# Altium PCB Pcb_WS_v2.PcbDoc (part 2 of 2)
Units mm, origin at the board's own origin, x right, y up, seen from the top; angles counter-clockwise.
Board outline 100 x 100 mm, 2 copper layers (Top Layer, Bottom Layer); 79 components, 52 nets, 324 pads, 930 vias.
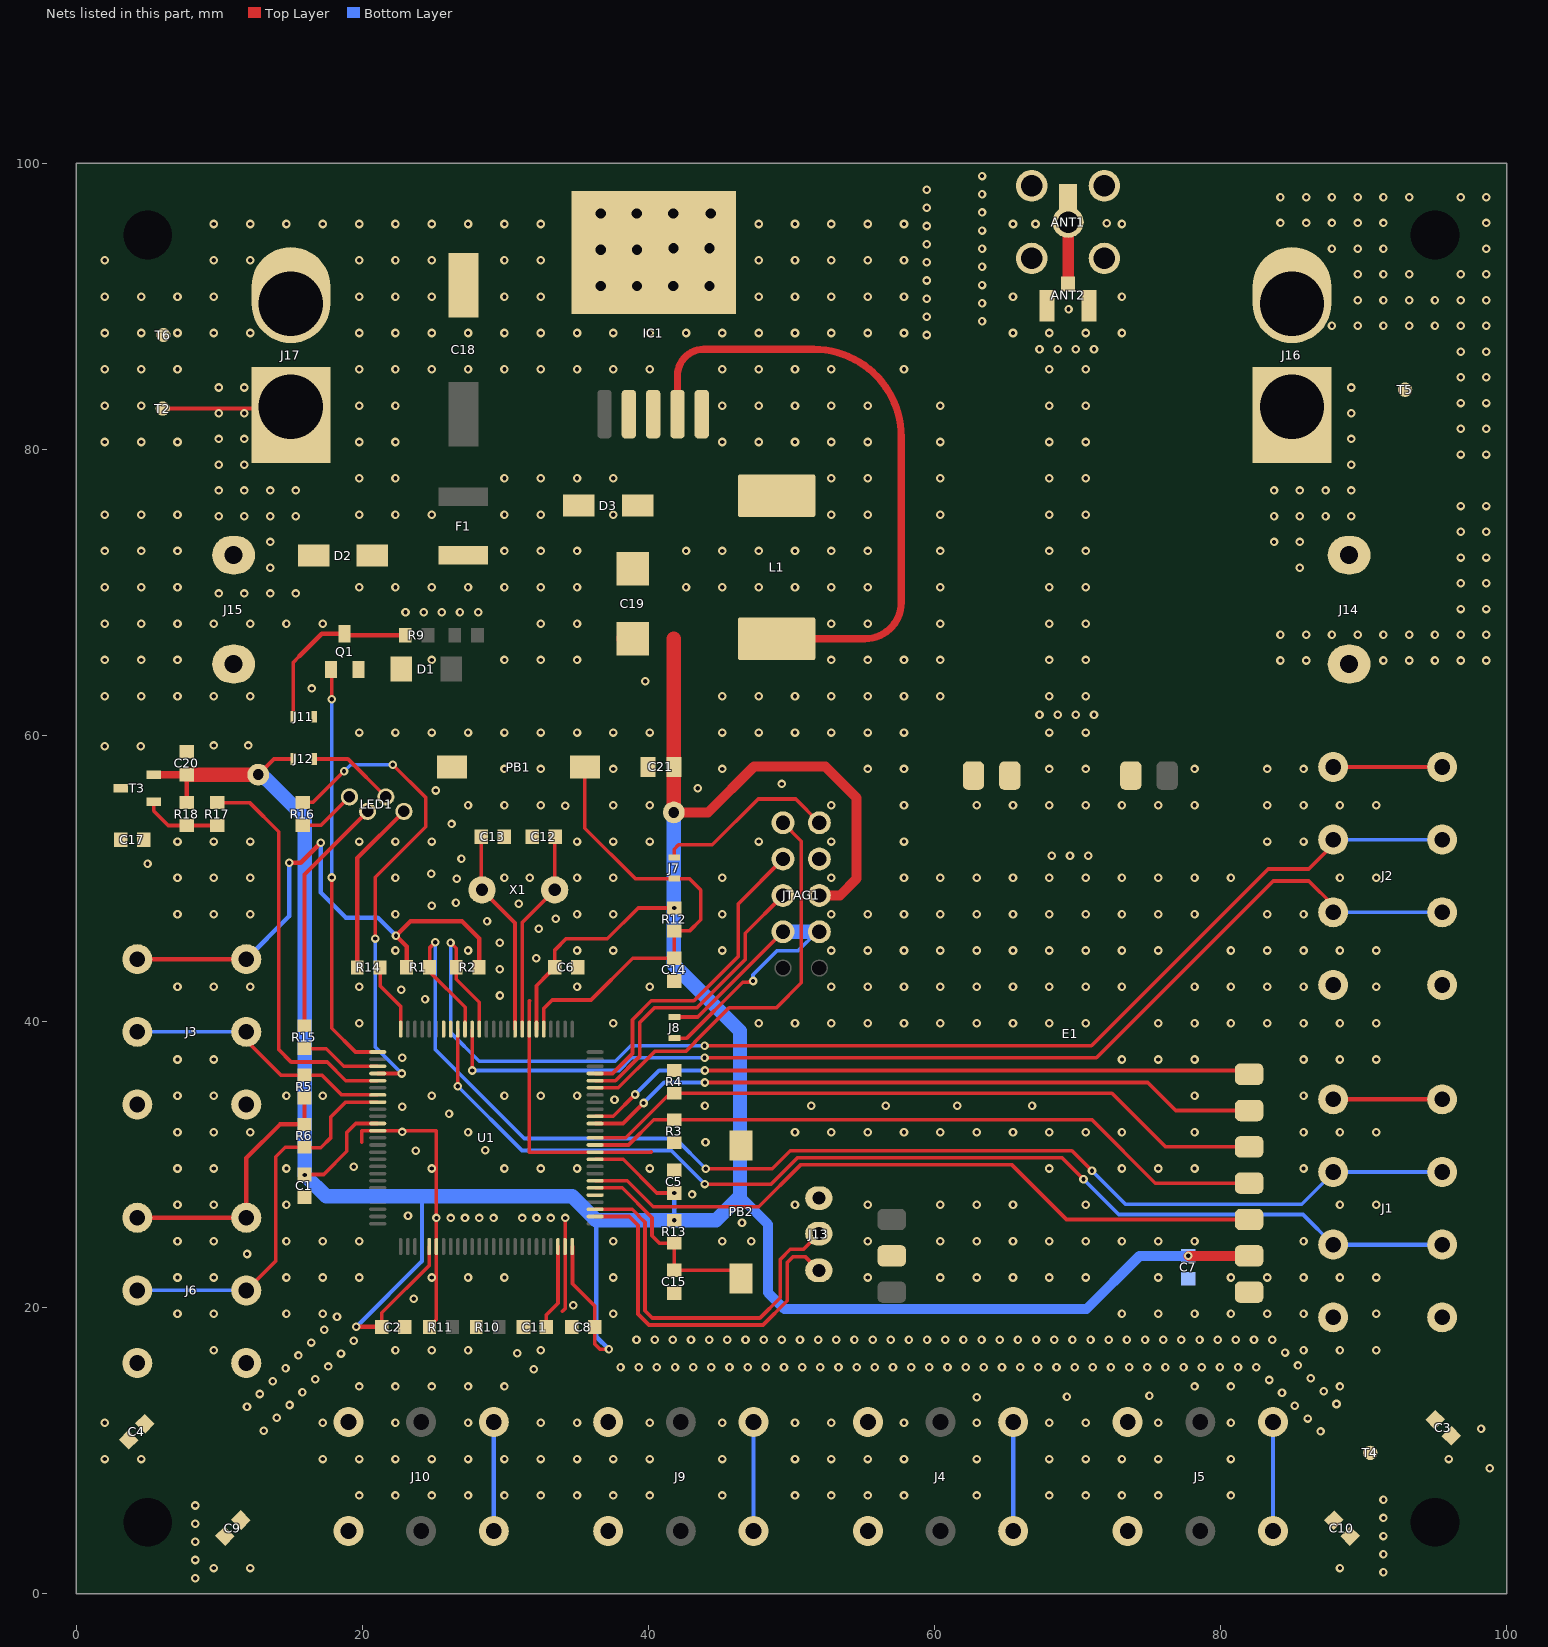
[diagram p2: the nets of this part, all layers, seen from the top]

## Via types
v1: diameter 0.6, hole 0.3, Top Layer to Bottom Layer, tented both sides, 918 vias
v2: diameter 1.27, hole 0.711, Top Layer to Bottom Layer, 12 vias

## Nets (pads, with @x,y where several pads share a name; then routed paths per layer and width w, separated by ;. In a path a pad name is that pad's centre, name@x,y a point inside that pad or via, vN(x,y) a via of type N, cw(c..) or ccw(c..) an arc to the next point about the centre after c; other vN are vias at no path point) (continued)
GND: ANT1.2 ANT2.2 C1.2 C2.2 C3.2 C4.2 C5.2 C6.2 C7.2 C8.2 C9.1 C10.1 C11.2 C12.1 C13.1 C14.1 C15.1 C17.1 C18.2 C19.2 C20.1 C21.1 D1.2 D3.2 E1.7 E1.9 E1.15 E1.16 E1.17 IC1.3 IC1.5 IC1.6 J1.4 J2.4 J3.1 J4.3 J5.3 J6.1 J9.3 J10.3 J11.2 J13.3 J15.1 J17.1 JTAG1.4 PB1.2 PB2.2 Q1.2 R3.1 R4.1 R10.2 R11.2 T6.1 U1.11 U1.32 U1.62 U1.81 U1.99 | length 45.7
  Top Layer w0.25: 19.953,31.559 19.953,32.372 U1.62@21.075,32.372 25.175,32.372 v1(25.175,26.272) U1.81@25.175,24.272 25.175,19.165 25.029,19.019 25.014,19.019 24.689,18.694 R11.2@24.689,18.644 ; 31.683,41.449 31.675,41.449 U1.32@31.675,39.472 31.675,30.872 U1.11@36.275,30.872 40.188,30.872 40.188,30.913 ; 33.988,19.75 34.175,19.938 U1.99@34.175,24.272 v1(34.175,26.272)
  other v1: 8.309,1.081 91.392,1.487 9.611,1.788 12.151,1.788 88.351,1.788 8.309,2.351 91.392,2.757 8.309,3.621 91.392,4.027 8.309,4.891 91.392,5.297 8.309,6.161 91.392,6.567 19.771,6.868 22.311,6.868 24.851,6.868 27.391,6.868 29.931,6.868 32.471,6.868 35.011,6.868 37.551,6.868 40.091,6.868 45.171,6.868 50.251,6.868 52.791,6.868 55.331,6.868 57.871,6.868 62.951,6.868 68.031,6.868 70.571,6.868 73.111,6.868 75.651,6.868 80.731,6.868 98.831,8.763 1.991,9.408 4.531,9.408 17.231,9.408 19.771,9.408 22.311,9.408 24.851,9.408 27.391,9.408 29.931,9.408 32.471,9.408 35.011,9.408 37.551,9.408 40.091,9.408 45.171,9.408 50.251,9.408 52.791,9.408 55.331,9.408 57.871,9.408 62.951,9.408 68.031,9.408 70.571,9.408 73.111,9.408 75.651,9.408 80.731,9.408 95.971,9.408 86.997,11.344 13.109,11.394 98.222,11.521 1.991,11.948 17.231,11.948 22.311,11.948 27.391,11.948 32.471,11.948 35.011,11.948 40.091,11.948 45.171,11.948 50.251,11.948 52.791,11.948 57.871,11.948 62.951,11.948 68.031,11.948 70.571,11.948 75.651,11.948 80.731,11.948 86.098,12.243 14.008,12.293 11.931,13.062 85.199,13.142 14.907,13.192 88.112,13.26 62.967,13.741 69.266,13.767 75.032,13.843 12.83,13.961 84.3,14.041 15.806,14.091 87.213,14.159 19.771,14.488 22.311,14.488 24.851,14.488 27.391,14.488 29.931,14.488 78.191,14.488 80.731,14.488 88.351,14.488 13.729,14.86 83.401,14.94 16.705,14.99 86.314,15.058 31.979,15.697 14.628,15.759 38.052,15.839 39.322,15.839 40.592,15.839 41.862,15.839 43.132,15.839 44.402,15.839 45.672,15.839 46.942,15.839 48.212,15.839 49.482,15.839 50.752,15.839 52.022,15.839 53.292,15.839 54.562,15.839 55.832,15.839 57.102,15.839 58.372,15.839 59.642,15.839 60.912,15.839 62.182,15.839 63.452,15.839 64.722,15.839 65.992,15.839 67.262,15.839 68.532,15.839 69.802,15.839 71.072,15.839 72.342,15.839 73.612,15.839 74.882,15.839 76.152,15.839 77.422,15.839 78.692,15.839 79.962,15.839 81.232,15.839 82.502,15.839 17.604,15.889 85.415,15.957 15.527,16.658 18.503,16.788 30.836,16.815 84.516,16.856 9.611,17.028 22.311,17.028 24.851,17.028 27.391,17.028 32.471,17.028 85.811,17.028 88.351,17.028 90.891,17.028 16.426,17.557 19.402,17.687 39.167,17.755 40.437,17.755 41.707,17.755 42.977,17.755 44.247,17.755 45.517,17.755 46.787,17.755 48.057,17.755 49.327,17.755 50.597,17.755 51.867,17.755 53.137,17.755 54.407,17.755 55.677,17.755 56.947,17.755 58.217,17.755 59.487,17.755 60.757,17.755 62.027,17.755 63.297,17.755 64.567,17.755 65.837,17.755 67.107,17.755 68.377,17.755 69.647,17.755 70.917,17.755 72.187,17.755 73.457,17.755 74.727,17.755 75.997,17.755 77.267,17.755 78.537,17.755 79.807,17.755 81.077,17.755 82.347,17.755 83.617,17.755 17.325,18.456 18.224,19.355 7.071,19.568 9.611,19.568 14.691,19.568 17.231,19.568 37.551,19.568 73.111,19.568 75.651,19.568 78.191,19.568 80.731,19.568 83.271,19.568 85.811,19.568 90.891,19.568 34.747,20.159 23.597,20.625 7.071,22.108 9.611,22.108 14.691,22.108 17.231,22.108 19.771,22.108 24.851,22.108 27.391,22.108 29.931,22.108 37.551,22.108 55.331,22.108 60.411,22.108 62.951,22.108 65.491,22.108 68.031,22.108 70.571,22.108 75.651,22.108 80.731,22.108 83.271,22.108 85.811,22.108 88.351,22.108 90.891,22.108 11.938,23.749 7.071,24.648 9.611,24.648 14.691,24.648 17.231,24.648 19.771,24.648 37.551,24.648 45.171,24.648 47.193,24.648 55.331,24.648 60.411,24.648 62.951,24.648 65.491,24.648 68.031,24.648 70.571,24.648 73.111,24.648 75.651,24.648 78.191,24.648 85.811,24.648 46.545,25.933 26.175,26.272 27.175,26.272 28.175,26.272 29.175,26.272 31.175,26.272 32.175,26.272 33.175,26.272 23.188,26.415 7.071,27.188 9.611,27.188 14.691,27.188 50.251,27.188 55.331,27.188 60.411,27.188 62.951,27.188 65.491,27.188 70.571,27.188 88.351,27.188 90.891,27.188 43.053,27.915 7.071,29.728 9.611,29.728 14.691,29.728 24.851,29.728 29.931,29.728 32.471,29.728 35.011,29.728 40.091,29.728 68.031,29.728 73.111,29.728 75.651,29.728 78.191,29.728 85.811,29.728 19.396,29.845 23.723,30.963 28.6,31.013 43.993,31.572 7.071,32.268 9.611,32.268 12.151,32.268 27.391,32.268 50.251,32.268 52.791,32.268 55.331,32.268 57.871,32.268 60.411,32.268 62.951,32.268 65.491,32.268 68.031,32.268 70.571,32.268 73.111,32.268 78.191,32.268 85.811,32.268 88.351,32.268 90.891,32.268 22.784,32.283 26.06,33.553 22.784,34.036 43.953,34.112 51.393,34.112 56.591,34.122 61.595,34.122 66.827,34.122 37.627,34.544 7.071,34.808 9.611,34.808 14.691,34.808 17.231,34.808 24.851,34.808 29.931,34.808 32.471,34.808 35.011,34.808 78.191,34.808 85.811,34.808 7.071,37.348 9.611,37.348 73.111,37.348 75.651,37.348 78.191,37.348 85.811,37.348 88.351,37.348 90.891,37.348 22.784,37.472 19.771,39.888 37.551,39.888 47.711,39.888 50.251,39.888 52.791,39.888 55.331,39.888 57.871,39.888 60.411,39.888 62.951,39.888 65.491,39.888 68.031,39.888 70.571,39.888 75.651,39.888 78.191,39.888 80.731,39.888 83.271,39.888 85.811,39.888 88.351,39.888 90.891,39.888 24.384,41.554 29.616,41.823 22.708,42.227 7.071,42.428 9.611,42.428 12.151,42.428 19.771,42.428 35.011,42.428 40.091,42.428 52.791,42.428 55.331,42.428 57.871,42.428 60.411,42.428 62.951,42.428 65.491,42.428 68.031,42.428 70.571,42.428 73.111,42.428 78.191,42.428 80.731,42.428 83.271,42.428 85.811,42.428 90.891,42.428 29.608,43.663 32.148,44.435 22.311,44.968 27.391,44.968 35.011,44.968 37.551,44.968 45.171,44.968 52.791,44.968 55.331,44.968 57.871,44.968 60.411,44.968 62.951,44.968 65.491,44.968 68.031,44.968 70.571,44.968 73.111,44.968 75.651,44.968 80.731,44.968 83.271,44.968 85.811,44.968 88.351,44.968 90.891,44.968 29.608,45.518 32.334,46.482 28.72,47.015 33.528,47.196 7.071,47.508 9.611,47.508 12.151,47.508 22.311,47.508 35.011,47.508 37.551,47.508 45.171,47.508 52.791,47.508 55.331,47.508 57.871,47.508 60.411,47.508 62.951,47.508 65.491,47.508 68.031,47.508 70.571,47.508 73.111,47.508 75.651,47.508 78.191,47.508 83.271,47.508 85.811,47.508 24.841,48.108 30.925,48.235 26.543,48.311 26.594,49.998 7.071,50.048 9.611,50.048 12.151,50.048 22.311,50.048 29.931,50.048 35.011,50.048 37.551,50.048 45.171,50.048 52.791,50.048 57.871,50.048 60.411,50.048 62.951,50.048 65.491,50.048 68.031,50.048 70.571,50.048 73.111,50.048 75.651,50.048 78.191,50.048 80.731,50.048 88.351,50.048 90.891,50.048 31.699,50.063 24.816,50.343 4.978,51.036 26.924,51.384 68.209,51.597 69.479,51.597 70.749,51.597 7.071,52.588 9.611,52.588 12.151,52.588 19.771,52.588 22.311,52.588 24.851,52.588 35.011,52.588 37.551,52.588 40.091,52.588 47.711,52.588 52.791,52.588 57.871,52.588 83.271,52.588 85.811,52.588 26.238,53.822 34.188,55.093 27.391,55.128 29.931,55.128 32.471,55.128 37.551,55.128 40.091,55.128 52.791,55.128 57.871,55.128 62.951,55.128 65.491,55.128 68.031,55.128 70.571,55.128 73.111,55.128 75.651,55.128 78.191,55.128 83.271,55.128 85.811,55.128 88.351,55.128 90.891,55.128 25.121,56.159 43.444,56.312 49.327,56.617 29.931,57.668 32.471,57.668 37.551,57.668 45.171,57.668 55.331,57.668 57.871,57.668 68.031,57.668 70.571,57.668 78.191,57.668 83.271,57.668 85.811,57.668 1.991,59.258 4.496,59.258 9.601,59.309 12.014,59.309 19.771,60.208 22.311,60.208 24.851,60.208 27.391,60.208 29.931,60.208 32.471,60.208 35.011,60.208 37.551,60.208 40.091,60.208 45.171,60.208 47.711,60.208 50.251,60.208 52.791,60.208 55.331,60.208 57.871,60.208 68.031,60.208 70.571,60.208 67.344,61.457 68.614,61.457 69.884,61.457 71.154,61.457 1.991,62.748 4.531,62.748 7.071,62.748 9.611,62.748 12.151,62.748 45.171,62.748 47.711,62.748 50.251,62.748 52.791,62.748 55.331,62.748 57.871,62.748 60.411,62.748 68.031,62.748 70.571,62.748 16.459,63.297 39.776,63.805 1.991,65.288 4.531,65.288 7.071,65.288 24.851,65.288 29.931,65.288 32.471,65.288 35.011,65.288 52.791,65.288 55.331,65.288 57.871,65.288 60.411,65.288 68.031,65.288 70.571,65.288 1.991,67.828 4.531,67.828 7.071,67.828 9.611,67.828 12.151,67.828 14.691,67.828 17.231,67.828 32.471,67.828 35.011,67.828 52.791,67.828 55.331,67.828 60.411,67.828 68.031,67.828 70.571,67.828 23.012,68.631 24.282,68.631 25.552,68.631 26.822,68.631 28.092,68.631 1.991,70.368 4.531,70.368 7.071,70.368 19.771,70.368 22.311,70.368 24.851,70.368 27.391,70.368 29.931,70.368 32.471,70.368 35.011,70.368 42.631,70.368 45.171,70.368 47.711,70.368 50.251,70.368 52.791,70.368 55.331,70.368 60.411,70.368 68.031,70.368 70.571,70.368 1.991,72.908 4.531,72.908 7.071,72.908 29.931,72.908 32.471,72.908 35.011,72.908 42.631,72.908 45.171,72.908 47.711,72.908 50.251,72.908 52.791,72.908 55.331,72.908 60.411,72.908 68.031,72.908 70.571,72.908 1.991,75.448 4.531,75.448 7.071,75.448 19.771,75.448 22.311,75.448 24.851,75.448 29.931,75.448 32.471,75.448 37.551,75.448 52.791,75.448 55.331,75.448 60.411,75.448 68.031,75.448 70.571,75.448 19.771,77.988 22.311,77.988 29.931,77.988 32.471,77.988 35.011,77.988 37.551,77.988 52.791,77.988 55.331,77.988 60.411,77.988 68.031,77.988 70.571,77.988 1.991,80.528 4.531,80.528 7.071,80.528 19.771,80.528 22.311,80.528 45.171,80.528 47.711,80.528 50.251,80.528 52.791,80.528 55.331,80.528 60.411,80.528 68.031,80.528 70.571,80.528 1.991,83.068 4.531,83.068 19.771,83.068 22.311,83.068 45.171,83.068 47.711,83.068 50.251,83.068 52.791,83.068 55.331,83.068 60.411,83.068 68.031,83.068 70.571,83.068 1.991,85.608 4.531,85.608 7.071,85.608 19.771,85.608 22.311,85.608 24.851,85.608 27.391,85.608 29.931,85.608 32.471,85.608 35.011,85.608 37.551,85.608 40.091,85.608 45.171,85.608 47.711,85.608 50.251,85.608 52.791,85.608 57.871,85.608 68.031,85.608 70.571,85.608 67.344,87.01 68.614,87.01 69.884,87.01 71.154,87.01 59.471,88.007 1.991,88.148 4.531,88.148 7.071,88.148 9.611,88.148 12.151,88.148 19.771,88.148 22.311,88.148 24.851,88.148 27.391,88.148 29.931,88.148 32.471,88.148 35.011,88.148 37.551,88.148 40.091,88.148 42.631,88.148 45.171,88.148 47.711,88.148 50.251,88.148 52.791,88.148 55.331,88.148 57.871,88.148 65.491,88.148 68.031,88.148 70.571,88.148 73.111,88.148 63.332,88.961 59.471,89.277 69.377,89.799 63.332,90.231 59.471,90.547 1.991,90.688 4.531,90.688 7.071,90.688 9.611,90.688 19.771,90.688 22.311,90.688 24.851,90.688 29.931,90.688 32.471,90.688 47.711,90.688 50.251,90.688 52.791,90.688 55.331,90.688 57.871,90.688 65.491,90.688 73.111,90.688 63.332,91.501 59.471,91.817 63.332,92.771 59.471,93.087 1.991,93.228 9.611,93.228 12.151,93.228 19.771,93.228 22.311,93.228 24.851,93.228 29.931,93.228 32.471,93.228 47.711,93.228 50.251,93.228 52.791,93.228 55.331,93.228 57.871,93.228 63.332,94.041 59.471,94.357 63.332,95.311 59.471,95.627 9.611,95.768 12.151,95.768 14.691,95.768 17.231,95.768 19.771,95.768 22.311,95.768 24.851,95.768 27.391,95.768 29.931,95.768 32.471,95.768 47.711,95.768 50.251,95.768 52.791,95.768 55.331,95.768 57.871,95.768 65.491,95.768 67.066,95.768 73.111,95.768 72.044,95.819 63.332,96.581 59.471,96.897 63.332,97.851 59.471,98.167 63.332,99.121
  other v2: 36.662,91.424 39.202,91.424 41.742,91.424 44.282,91.424 36.662,93.964 39.202,93.964 41.752,94.069 44.282,94.069 36.662,96.504 39.18,96.504 41.742,96.504 44.355,96.504
GND-SOLAR: J14.2 J16.1
  other v1: 84.193,65.246 85.993,65.246 91.393,65.246 93.193,65.246 94.993,65.246 96.793,65.246 98.593,65.246 84.193,67.046 85.993,67.046 87.793,67.046 89.593,67.046 91.393,67.046 93.193,67.046 94.993,67.046 96.793,67.046 98.593,67.046 96.793,68.846 98.593,68.846 96.793,70.646 98.593,70.646 96.793,72.446 98.593,72.446 96.793,74.246 98.593,74.246 96.793,76.046 98.593,76.046 96.793,79.646 98.593,79.646 96.793,81.446 98.593,81.446 96.793,83.246 98.593,83.246 96.793,85.046 98.593,85.046 96.793,86.846 98.593,86.846 87.793,88.646 89.593,88.646 91.393,88.646 93.193,88.646 94.993,88.646 96.793,88.646 98.593,88.646 89.593,90.446 91.393,90.446 93.193,90.446 94.993,90.446 96.793,90.446 98.593,90.446 89.593,92.246 91.393,92.246 93.193,92.246 96.793,92.246 98.593,92.246 87.793,94.046 89.593,94.046 91.393,94.046 98.593,94.046 84.193,95.846 85.993,95.846 87.793,95.846 89.593,95.846 91.393,95.846 98.593,95.846 84.193,97.646 85.993,97.646 87.793,97.646 89.593,97.646 91.393,97.646 93.193,97.646 96.793,97.646 98.593,97.646
MISO: JTAG1.3 U1.22 | length 22.9
  Top Layer w0.254: U1.22@36.275,36.372 37.495,36.372 38.888,37.764 38.888,40.132 40.205,41.449 43.181,41.449 46.277,44.544 46.277,48.227 JTAG1.3@49.412,51.363
MOSI: JTAG1.5 U1.21 | length 21
  Top Layer w0.254: U1.21@36.275,35.872 37.694,35.872 39.382,37.559 39.382,39.928 40.409,40.955 43.386,40.955 46.771,44.34 46.771,46.181 JTAG1.5@49.412,48.823
NetANT1_1: ANT1.1 ANT2.1 pad.4 | length 4.3
  Top Layer w0.8: ANT2.1@69.341,91.562 ANT1.1@69.341,95.902
NetC11_1: C11.1 U1.98 | length 6
  Top Layer w0.254: C11.1@32.867,18.644 32.867,19.507 33.675,20.315 U1.98@33.675,24.272
NetC12_2: C12.2 U1.33 X1.1 | length 14.4
  Top Layer w0.254: U1.33@31.175,39.472 31.175,46.934 X1.1@33.448,49.207 33.448,52.919 C12.2@33.475,52.919
NetC13_2: C13.2 U1.34 X1.2 | length 14.5
  Top Layer w0.254: C13.2@28.273,52.919 C13.2@28.319,52.919 28.319,49.207 X1.2@28.368,49.207 30.675,46.9 U1.34@30.675,39.472
NetD2_1: D2.1 F1.1
NetD3_1: D3.1 IC1.2 L1.1
NetJ7_1: J7.1 JTAG1.2 | length 12.9
  Top Layer w0.254: J7.1@41.806,51.471 41.806,52.055 42.111,52.36 44.473,52.36 47.674,55.56 50.295,55.56 JTAG1.2@51.952,53.903
NetJ11_1: J11.1 Q1.3 R9.2 | length 12.5
  Top Layer w0.25: J11.1@15.159,61.308 15.159,65.112 15.591,65.544
  Top Layer w0.3: 15.591,65.544 17.161,67.114 Q1.3@18.755,67.114 18.862,67.007 R9.2@22.994,67.007
NetJ12_2: J12.2 LED1.A | length 6.1
  Top Layer w0.25: J12.2@16.633,58.362 18.989,58.362 LED1.A@21.636,55.714
NetLED1_B: LED1.B R15.2 | length 16.8
  Top Layer w0.3: R15.2@15.951,39.709 15.951,50.283 LED1.B@20.366,54.698
NetLED1_G: LED1.G R14.2 | length 12.3
  Top Layer w0.3: R14.2@19.643,43.786 19.643,51.435 LED1.G@22.906,54.698
NetLED1_R: LED1.R R16.2 | length 4.1
  Top Layer w0.25: R16.2@15.82,53.714 17.096,53.714 LED1.R@19.096,55.714
NetR17_2: R17.2 R18.2 T3.1 | length 5.5
  Top Layer w0.254: T3.1@5.41,55.364 5.41,54.732 6.428,53.714 R18.2@7.717,53.714
  Top Layer w0.3: R18.2@7.717,53.714 R17.2@9.844,53.714
ON5V: J8.1 J8.2 JTAG1.7 JTAG1.8 | length 25.9
  Top Layer w0.254: J8.2@41.825,38.847 42.691,38.847 46.605,42.76 46.995,42.76 47.005,42.77 47.25,42.77 v1(47.316,42.837) ; J8.1@41.825,40.32 43.45,40.32 JTAG1.7@49.412,46.283
  Bottom Layer w0.254: v1(47.316,42.837) 47.316,43.268 48.992,44.945 50.465,44.945 51.803,46.283 JTAG1.8@51.952,46.283
  Bottom Layer w1: JTAG1.7@49.412,46.283 JTAG1.8@51.803,46.283
Pin2Button: C15.2 PB2.1 R13.1 U1.6 | length 14.7
  Top Layer w0.254: U1.6@36.275,28.372 38.173,28.372 40.255,26.29 40.255,25.031 40.777,24.509 R13.1@41.8,24.509 C15.2@41.8,22.604 45.917,22.604 PB2.1@46.482,22.039
Pin3AUX: E1.5 U1.7 | length 49.3
  Top Layer w0.254: U1.7@36.275,28.872 38.521,28.872 40.339,27.053 47.705,27.053 50.63,29.978 65.419,29.978 69.237,26.16 E1.5@82,26.16
Pin5: U1.5
Pin6M1: E1.2 U1.15 | length 47.7
  Top Layer w0.254: U1.15@36.275,32.872 38.227,32.872 v1(39.663,34.308) ; v1(43.953,35.74) 74.907,35.74 76.867,33.78 E1.2@82,33.78
  Bottom Layer w0.254: v1(39.663,34.308) 41.096,35.74 v1(43.953,35.74)
Pin7M0: E1.1 U1.16 | length 47.2
  Top Layer w0.254: U1.16@36.275,33.372 37.539,33.372 v1(39.069,34.902) ; v1(43.953,36.58) 81.74,36.58 E1.1@82,36.32
  Bottom Layer w0.254: v1(39.069,34.902) 40.748,36.58 v1(43.953,36.58)
Pin32DS1: J6.2 R6.2 U1.58 | length 27.4
  Top Layer w0.254: J6.2@11.88,21.203 13.937,23.261 13.937,30.543 14.607,31.213 R6.2@15.947,31.213 15.982,31.178 17.087,31.178 17.798,31.889 17.798,33.337 18.833,34.372 U1.58@21.075,34.372
  Bottom Layer w0.254: J6.2@4.26,21.203 J6.2@11.88,21.203
Pin33DS2: J3.2 R5.2 U1.57 | length 19
  Top Layer w0.254: J3.2@11.88,39.283 11.88,38.671 14.293,36.258 R5.2@15.951,36.258 17.166,36.258 18.552,34.872 U1.57@21.075,34.872
  Bottom Layer w0.254: J3.2@4.26,39.283 J3.2@11.88,39.283
Pin35FET: R17.1 U1.55 | length 28.2
  Top Layer w0.25: R17.1@9.844,55.314 12.106,55.314 14.143,53.276 14.143,38.043 15.014,37.172 17.534,37.172 18.834,35.872 U1.55@21.075,35.872
Pin36Data: R16.1 U1.54 | length 33.9
  Top Layer w0.25: R16.1@15.82,55.314 15.837,55.331 16.548,55.331 v1(18.718,57.5) ; v1(20.903,45.806) 20.903,50.096 24.433,53.626 24.433,55.667 v1(22.133,57.967) ; U1.54@21.075,36.372 v1(22.75,36.372)
  Bottom Layer w0.25: v1(18.718,57.5) 19.184,57.967 v1(22.133,57.967) ; v1(20.903,45.806) 20.903,38.219 v1(22.75,36.372)
Pin37Net: R15.1 U1.53 | length 5.6
  Top Layer w0.254: R15.1@15.951,38.109 17.466,38.109 18.704,36.872 U1.53@21.075,36.872
Pin38Bug: R14.1 U1.50 | length 4.9
  Top Layer w0.254: R14.1@21.243,43.786 21.243,42.492 22.675,41.06 U1.50@22.675,39.472
Pin41EnLevelPin: Q1.1 U1.51 | length 29
  Top Layer w0.25: Q1.1@17.81,64.62 17.852,64.577 v1(17.852,62.547) ; v1(17.852,50.076) 17.852,39.535 19.515,37.872 U1.51@21.075,37.872
  Bottom Layer w0.25: v1(17.852,50.076) v1(17.852,62.547)
Pin42CLSHT1: J1.3 U1.42 | length 78.9
  Top Layer w0.254: v1(26.675,35.472) U1.42@26.675,39.472 ; v1(43.938,28.638) 48.592,28.638 50.425,30.472 68.925,30.472 v1(70.425,28.972)
  Bottom Layer w0.254: v1(26.675,35.472) 31.159,30.988 41.588,30.988 v1(43.938,28.638) ; v1(70.425,28.972) 72.882,26.514 85.769,26.514 J1.3@87.88,24.404
  Bottom Layer w0.3: J1.3@87.88,24.404 J1.3@95.5,24.404
Pin43DTSHT1: J1.2 R1.1 U1.41 | length 91.7
  Top Layer w0.254: v1(25.099,45.544) 24.698,45.142 R1.1@24.698,43.8 24.698,43.484 27.183,40.999 27.183,39.951 27.175,39.943 U1.41@27.175,39.472 ; v1(44.014,29.705) 48.658,29.705 49.925,30.972 69.613,30.972 v1(71.019,29.566)
  Bottom Layer w0.254: v1(25.099,45.544) 25.099,38.047 31.321,31.826 41.892,31.826 v1(44.014,29.705) ; v1(71.019,29.566) 73.363,27.222 85.675,27.222 87.88,29.426 J1.2@87.88,29.484 J1.2@95.5,29.484
Pin44CLSHT2: J2.3 U1.40 | length 77.4
  Top Layer w0.254: v1(27.675,36.58) U1.40@27.675,39.472 ; v1(43.925,37.472) 71.324,37.472 83.683,49.831 86.175,49.831 87.88,48.126 J2.3@87.88,47.644
  Bottom Layer w0.254: v1(27.675,36.58) 37.941,36.58 38.833,37.472 v1(43.925,37.472) ; J2.3@87.88,47.644 J2.3@95.5,47.644
Pin45DTSHT2: J2.2 R2.1 U1.39 | length 90
  Top Layer w0.254: v1(26.166,45.519) 26.566,45.119 R2.1@26.566,43.8 26.566,42.962 28.175,41.353 U1.39@28.175,39.472 ; v1(43.925,38.312) 70.976,38.312 83.335,50.671 86.175,50.671 87.88,52.376 J2.2@87.88,52.724
  Bottom Layer w0.254: v1(26.166,45.519) 26.166,39.231 28.175,37.222 37.675,37.222 38.765,38.312 v1(43.925,38.312) ; J2.2@87.88,52.724 J2.2@95.5,52.724
RESET: C14.2 J7.2 PB1.1 R12.1 U1.30 | length 32.3
  Top Layer w0.254: U1.30@32.675,39.472 32.675,40.917 33.272,41.514 35.99,41.514 38.911,44.435 C14.2@41.8,44.435 R12.1@41.8,46.34 42.873,46.34 43.66,47.127 43.66,49.196 42.859,49.998 J7.2@41.806,49.998 39.088,49.998 35.558,53.528 PB1.1@35.558,57.789
RX_2560: J13.1 U1.2 | length 26.4
  Top Layer w0.25: U1.2@36.275,26.372 38.669,26.372 39.273,25.768 39.273,19.552 40.041,18.784 48.015,18.784 49.717,20.486 49.717,23.156 50.132,23.57 50.953,23.57 J13.1@51.918,22.606
RX_Lora: E1.3 R4.2 U1.13 | length 48.6
  Top Layer w0.254: U1.13@36.275,31.872 38.412,31.872 41.527,34.986 R4.2@41.8,34.986 72.41,34.986 76.157,31.24 E1.3@82,31.24
SCK: JTAG1.1 U1.20 | length 29.2
  Top Layer w0.254: U1.20@36.275,35.372 37.893,35.372 40.454,37.933 42.63,37.933 43.258,38.56 43.258,38.588 45.642,40.972 48.956,40.972 50.696,42.712 50.696,52.619 JTAG1.1@49.412,53.903
SCL: U1.43
SDA: U1.44
TX_2560: J13.2 U1.3 | length 26.5
  Top Layer w0.25: U1.3@36.275,26.872 38.876,26.872 39.335,26.413 39.335,26.399 39.763,25.971 39.763,19.77 40.259,19.274 47.798,19.274 49.217,20.693 49.217,23.363 49.924,24.07 50.848,24.07 51.918,25.14 J13.2@51.918,25.171
TX_Lora: E1.4 R3.2 U1.12 | length 48.3
  Top Layer w0.254: U1.12@36.275,31.372 38.611,31.372 40.371,33.132 R3.2@41.8,33.132 71.015,33.132 75.447,28.7 E1.4@82,28.7
VBAT: D2.2 J15.2 J17.2 T2.1 | length 9
  Top Layer w0.254: T2.1@6.043,82.865 14.865,82.865 ccw(c14.865,83) J17.2@15,83
  other v1: 9.948,69.939 11.748,69.939 13.548,69.939 15.348,69.939 13.548,71.739 13.548,73.539 9.948,75.339 11.748,75.339 13.548,75.339 15.348,75.339 9.948,77.139 11.748,77.139 13.548,77.139 15.348,77.139 9.948,78.939 11.748,78.939 9.948,80.739 11.748,80.739 9.948,82.539 11.748,82.539 9.948,84.339 11.748,84.339
VCC: C1.1 C2.1 C5.1 C6.1 C7.1 C8.1 C19.1 C20.2 C21.2 E1.6 IC1.4 J12.1 JTAG1.6 L1.2 pad.TP-VCC R12.2 R13.2 R18.1 T3.2 U1.10 U1.31 U1.61 U1.80 U1.100 | length 295.8
  Top Layer w0.25: U1.100@34.69,24.272 34.69,21.664 36.242,20.113 C8.1@36.242,18.644 36.242,17.454 36.612,17.083 v1(37.239,17.083)
  Top Layer w0.254: C1.1@15.951,29.308 17.294,29.308 18.916,30.93 18.916,32.245 19.543,32.872 U1.61@21.075,32.872 ; C2.1@21.362,18.644 21.362,19.634 24.675,22.948 U1.80@24.675,24.272 ; U1.31@32.175,39.472 32.175,42.513 33.089,43.427 33.114,43.427 33.462,43.775 C6.1@33.462,43.8 33.462,45.011 34.235,45.783 37.13,45.783 39.288,47.94 v1(41.8,47.94) ; U1.10@36.275,30.372 38.233,30.372 40.59,28.014 v1(41.8,28.014)
  Top Layer w0.3: R18.1@7.717,55.314 C20.2@7.717,57.264 ; pad.TP-VCC@12.717,57.264 13.815,58.362 J12.1@15.159,58.362 ; v1(19.579,18.656) 21.349,18.656 C2.1@21.362,18.644
  Top Layer w0.5: T3.2@5.41,57.264 C20.2@7.717,57.264 ; IC1.4@42.031,82.475 42.031,85.167 cw(c43.872,85.167) 43.872,87.007 51.563,87.007 cw(c51.563,80.891) 57.679,80.891 57.679,69.309 cw(c55.139,69.309) 55.139,66.769 L1.2@48.969,66.769
  Top Layer w0.7: pad.TP-VCC@41.775,54.628 44.17,54.628 47.367,57.825 52.376,57.825 54.562,55.639 54.562,49.998 53.387,48.823 JTAG1.6@51.952,48.823 ; v1(77.75,23.62) E1.6@82,23.62
  Top Layer w1: C20.2@7.717,57.264 pad.TP-VCC@12.717,57.264 ; pad.TP-VCC@41.775,54.628 C21.2@41.775,57.804 41.775,66.769
  Top Layer w2.25: C19.1@38.911,66.769 C19.1@38.911,66.775
  Bottom Layer w0.3: v1(19.579,18.656) 24.175,23.252 24.175,27.78 ; 36.355,26.104 36.355,17.968 v1(37.239,17.083) ; v1(41.8,26.109) v1(41.8,28.014)
  Bottom Layer w0.7: 46.404,27.78 48.357,25.827 48.357,21.043 49.5,19.9 70.633,19.9 74.353,23.62 v1(77.75,23.62)
  Bottom Layer w1: pad.TP-VCC@12.717,57.264 12.859,57.264 13.121,57.002 13.245,57.002 15.974,54.272 v1(15.974,29.279) 17.473,27.78 24.175,27.78 34.678,27.78 36.355,26.104 44.727,26.104 46.404,27.78 46.404,39.337 41.775,43.966 pad.TP-VCC@41.775,54.628
VCC_Sensor: C3.1 C4.1 C9.2 C10.2 C17.2 J1.1 J2.1 J3.3 J4.1 J5.1 J6.3 J9.1 J10.1 R1.2 R2.2 R5.1 R6.1 T3.3 T4.1 | length 104
  Top Layer w0.3: J6.3@4.26,26.283 J6.3@11.88,26.283 11.88,30.455 14.238,32.813 R6.1@15.947,32.813 15.947,34.655 R5.1@15.951,34.658 ; J3.3@4.26,44.363 J3.3@11.88,44.363 ; v1(14.876,51.104) 15.689,51.104 v1(17.086,52.501) ; R1.2@23.098,43.8 23.098,45.245 v1(22.344,45.999) 23.36,47.015 26.967,47.015 28.166,45.815 R2.2@28.166,43.8 ; J1.1@87.88,34.564 J1.1@95.5,34.564 ; J2.1@87.88,57.804 J2.1@95.5,57.804
  Bottom Layer w0.3: J3.3@11.88,44.363 14.876,47.36 v1(14.876,51.104) ; v1(17.086,52.501) 17.086,49.021 18.839,47.269 21.074,47.269 v1(22.344,45.999) ; J10.1@29.188,4.38 J10.1@29.188,12 ; J9.1@47.348,4.38 J9.1@47.348,12 ; J4.1@65.508,4.38 J4.1@65.508,12 ; J5.1@83.668,4.38 J5.1@83.668,12
VSOLAR: J14.1 J16.2 T5.1
  other v1: 85.548,71.739 83.748,73.539 85.548,73.539 83.748,75.339 85.548,75.339 87.348,75.339 89.148,75.339 83.748,77.139 85.548,77.139 87.348,77.139 89.148,77.139 89.148,78.939 89.148,80.739 89.148,82.539 89.148,84.339
pads on no net: E1.8 E1.10 E1.11 E1.12 E1.13 E1.14 E1.18 HOLE1.1 HOLE2.1 HOLE3.1 HOLE4.1 JTAG1.9 JTAG1.10 U1.1 U1.4 U1.8 U1.9 U1.14 U1.17 U1.18 U1.19 U1.23 U1.24 U1.25 U1.26 U1.27 U1.28 U1.29 U1.35 U1.36 U1.37 U1.38 U1.45 U1.46 U1.47 U1.48 U1.49 U1.52 U1.56 U1.59 U1.60 U1.63 U1.64 U1.65 U1.66 U1.67 U1.68 U1.69 U1.70 U1.71 U1.72 U1.73 U1.74 U1.75 U1.76 U1.77 U1.78 U1.79 U1.82 U1.83 U1.84 U1.85 U1.86 U1.87 U1.88 U1.89 U1.90 U1.92 U1.93

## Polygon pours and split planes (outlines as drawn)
GND on Top Layer "AutoNaming" (solid, remove dead copper, pour order 58): 0,100 0,7.86 7.504,7.86 19.279,19.634 20.296,19.634 23.675,23.014 23.675,24.272 34.675,24.272 34.675,21.679 36.242,20.113 36.242,17.454 36.612,17.083 83.397,17.083 92.62,7.86 100,7.86 100,59.74 80.51,59.74 80.51,52.069 58.372,52.069 58.372,62.28 61.493,62.28 61.493,85.14 60.19,85.14 60.19,100
GND on Top Layer "AutoNaming" (solid, remove dead copper, pour order 40): 7.699,0 7.699,6.776 19.579,18.656 21.349,18.656 21.349,19.622 24.675,22.948 24.675,24.272 34.675,24.272 34.675,21.679 36.242,20.113 36.242,17.454 36.612,17.083 37.349,16.347 82.985,16.347 92.052,7.279 92.052,0
GND on Top Layer "AutoNaming" (solid, remove dead copper, pour order 48): 60.147,59.792 60.147,54.75 78.649,54.75 78.649,59.792 71.839,59.792 71.839,87.732 75.387,87.732 75.387,100.052 62.687,100.052 62.687,87.732 66.759,87.732 66.759,59.792
CheckLevel on Top Layer "Top Layer-NetC17_1 2" (solid, pour order 10): 25.22,84.821 28.903,84.821 28.903,75.931 25.22,75.931
GND on Top Layer "AutoNaming" (solid, pour order 60): 68.532,51.153 70.425,51.153 70.425,56.502 68.532,56.502
VCC_Sensor on Top Layer "AutoNaming" (solid, remove dead copper, pour order 20): 1,49.669 1,15.01 14.76,1.25 84.779,1.25 98.5,14.971 98.5,59.778 93.671,59.778 93.671,16.741 83.038,6.108 17.318,6.108 6.066,17.36 6.066,49.669
CheckLevel on Top Layer "Top Layer-NetC17_1" (solid, pour order 18): 28.903,79.741 cw(c29.944,79.741) 29.944,80.782 30.071,80.782 30.071,84.821 25.22,84.821 25.22,79.741
NetD3_1 on Top Layer "Top Layer-NetD3_1" (solid, pour order 16): 38.123,75.194 51.738,75.194 51.738,78.369 41.755,78.369 cw(c41.755,80.986) 39.139,80.986 39.139,83.932 ccw(c38.885,83.932) 38.885,84.186 38.377,84.186 ccw(c38.377,83.932) 38.123,83.932
CheckLevel on Top Layer "Top Layer-NetC17_1 1" (solid, pour order 12): 25.22,84.821 36.752,84.821 cw(c36.752,84.135) 37.437,84.135 37.437,81.011 cw(c37.209,81.011) 37.209,80.782 25.22,80.782
NetD2_1 on Top Layer "Top Layer-NetD2_1" (solid, pour order 8): 19.581,71.308 29.081,71.308 29.081,73.874 19.581,73.874
VBAT on Top Layer "Top Layer-VBAT" (solid, pour order 4): 17.727,71.765 cw(c15.187,71.765) 15.187,69.225 11.047,69.225 cw(c11.047,71.765) 8.507,71.765 8.507,83.145 cw(c11.047,83.145) 11.047,85.685 17.727,85.685
GND-SOLAR on Top Layer "Top Layer-GND-SOLAR" (solid, pour order 0): 82.243,90.587 82.243,96.859 cw(c84.658,96.859) 84.658,99.274 99.337,99.274 99.337,64.958 cw(c96.797,64.958) 96.797,62.418 85.367,62.418 cw(c85.367,65.542) 82.243,65.542 cw(c85.075,65.542) 85.075,68.374 93.025,68.374 ccw(c93.025,71.435) 96.086,71.435 96.086,84.211 ccw(c92.86,84.211) 92.86,87.437 84.961,87.437
no net on Top Layer "AutoNaming" (solid, pour order 26): 0,0
no net on Top Layer "AutoNaming" (solid, pour order 22): 0,0
no net on Top Layer "Top Layer-No Net" (solid, pour order 14): 38.174,83.221
GND on Bottom Layer "AutoNaming" (solid, remove dead copper, pour order 54): 0,100 0,7.899 7.578,7.899 24.175,24.495 24.175,27.78 34.678,27.78 36.355,26.104 36.355,18.854 38.143,17.066 83.414,17.066 92.581,7.899 100,7.899 100,59.74 80.51,59.74 80.51,52.12 58.372,52.12 58.372,62.28 61.493,62.28 61.493,85.14 60.19,85.14 60.19,100
GND on Bottom Layer "AutoNaming" (solid, remove dead copper, pour order 36): 7.696,0 7.696,6.773 24.175,23.252 24.175,27.78 34.678,27.78 36.355,26.104 36.355,17.968 37.976,16.347 82.993,16.347 92.05,7.29 92.05,0.025
GND on Bottom Layer "AutoNaming" (solid, remove dead copper, pour order 62): 60.147,59.792 60.147,54.75 78.649,54.75 78.649,59.792 71.839,59.792 71.839,87.732 75.387,87.732 75.387,100.052 62.687,100.052 62.687,87.732 66.759,87.732 66.759,59.792
VBAT on Bottom Layer "Bottom Layer-VBAT" (solid, pour order 6): 17.727,71.765 cw(c15.187,71.765) 15.187,69.225 11.047,69.225 cw(c11.047,71.765) 8.507,71.765 8.507,83.145 cw(c11.047,83.145) 11.047,85.685 17.727,85.685
GND-SOLAR on Bottom Layer "Bottom Layer-GND-SOLAR" (solid, pour order 2): 82.243,90.612 82.243,96.759 cw(c84.783,96.759) 84.783,99.299 99.312,99.299 99.312,64.984 cw(c96.772,64.984) 96.772,62.444 85.425,62.444 cw(c85.425,65.625) 82.243,65.625 cw(c84.998,65.625) 84.998,68.38 90.51,68.38 ccw(c90.51,70.908) 93.038,70.908 93.038,84.897 ccw(c90.498,84.897) 90.498,87.437 84.961,87.437

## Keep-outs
Keep-Out Layer:
  the board outline again, w0.2

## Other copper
Top Layer:
  region net VCC_Sensor: 1,57.784 1,48.78 5.66,48.78 5.66,49.669 5.403,49.669 cw(c5.403,51.495) 3.577,51.495 3.577,57.784
  region net VCC: 48.969,68.269 37.437,68.269 37.437,65.269 39.975,65.269 cw(c39.975,63.971) 41.273,63.971 41.273,63.848 42.268,63.848 cw(c43.689,63.848) 43.689,65.269 48.969,65.269
  region net VSOLAR: 82.243,85.761 82.243,73.137 ccw(c85.977,73.137) 85.977,69.403 92.149,69.403 ccw(c92.149,71.943) 94.689,71.943 94.689,83.221 ccw(c92.149,83.221) 92.149,85.761
  pour cut-out: 71.197,37.198 71.197,36.944 71.451,36.944 71.451,37.198
  pour cut-out: 98.593,15.058 98.593,14.804 99.75,14.804 99.75,15.058
  pour cut-out: 84.042,1.25 84.042,0.264 85,0.264 85,1.25
  pour cut-out: 14.587,1.25 14.587,0.246 14.841,0.246 14.841,1.25
  pour cut-out: 0.246,14.94 0.246,14.75 1,14.75 1,14.94
  pour cut-out: 0.323,58 0.323,57.751 1,57.751 1,58
  pour cut-out: 72.548,35.381 72.548,35.127 72.802,35.127 72.802,35.381
  pour cut-out: 86.047,50.342 86.047,50.088 86.301,50.088 86.301,50.342
  pour cut-out: 74.923,36.27 74.923,36.016 75.177,36.016 75.177,36.27
  pour cut-out: 100.322,36.586
  pour cut-out: 100.322,36.586
  region: 25.175,24.272
Bottom Layer:
  region net VSOLAR: 82.243,85.761 82.243,73.797 ccw(c84.783,73.797) 84.783,71.257 88.974,71.257 ccw(c88.974,72.756) 90.473,72.756 90.473,83.221 ccw(c87.933,83.221) 87.933,85.761
Multi-Layer:
  pour cut-out: 0,60.681 17.301,60.681 17.301,63.094 41.03,63.094 41.03,61.894 18.222,61.894 18.222,59.715 0,59.715

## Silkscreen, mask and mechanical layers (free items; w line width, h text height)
Top Overlay:
  drawing of 802 lines, arcs and shapes, not listed
  text "-" at 82.093,96.241 h10
  text "-" at 11.862,96.215 h10
  text "FEMALE" at 19.5,90.995 h1.8 r270
  text "FEMALE" at 80.333,80.403 h1.8 r90
  text "+BAT" at 0.66,76.657 h4
  text "+SOLAR" at 89.179,76.581 h3
  text "+" at 15.25,73.764 h5 r90
  text "+" at 87.35,73.75 h5 r90
  text "SENSOR NODE / V3.1" at 68.133,70.339 h1.2
  text "-" at 15.25,63.5 h7 r90
  text "-" at 87.35,63.5 h7 r90
  text "RESET" at 29.093,60.662 h0.8
  text "T1" at 13,55.079 h0.8 r90
  text "T1" at 40.488,53.756 h0.8 r90
  text "G" at 50.048,27.391 h0.8 r90
  text "TX" at 50.124,24.572 h0.8 r90
  text "RX" at 50.124,21.93 h0.8 r90
Bottom Overlay:
  drawing of 873 lines, arcs and shapes, not listed
  text "SENSOR NODE V3.1 / Model: MultiSensor_LR433.1W / QTech Vietnam / 09/2019 / fps.qtechvietnam@gmail.com" at 53.144,75.339 h1
  text "CONNECTOR MAPPING" at 39.753,41.25 h1
  text "DS 01" at 36.753,39 h1
  text "1" at 39.75,39 h1
  text "SOLDER JUMP" at 67.5,39 h0.9
  text "TEST POINT" at 78,39 h1
  text "Back side" at 21.25,37.5 h1
  text "DS 02" at 36.753,37 h1
  text "2" at 39.75,37 h1
  text "J7" at 67,37 h1
  text "VCC" at 73,37 h1
  text "T1" at 77.5,37 h1
  text "Wind Direction" at 36.753,35 h1
  text "3" at 39.753,35 h1
  text "J8" at 67,35 h1
  text "VBAT" at 73.5,35 h1
  text "T2" at 77.5,35 h1
  text "Enable Prog." at 63.75,34.75 h1
  text "Wind Speed" at 36.753,33 h1
  text "4" at 39.753,33 h1
  text "Dis. Q1" at 64,33 h1
  text "J11" at 67.5,33 h1
  text "VSEN" at 73.5,33 h1
  text "T4" at 77.5,33 h1
  text "8" at 46.003,32.75 h3
  text "Water Pressure" at 36.753,31 h1
  text "5" at 39.753,31 h1
  text "LED OFF" at 64.25,31 h1
  text "J12" at 67.5,31 h1
  text "VSOLAR" at 74.25,31 h1
  text "T5" at 77.5,31 h1
  text "1" at 21.253,30.75 h3
  text "Air Pressure" at 36.753,29 h1
  text "6" at 39.753,29 h1
  text "GND" at 73,29 h1
  text "T6" at 77.5,29 h1
  text "Manual" at 60.503,27.51 h1
  text "SHT30 Soil" at 36.753,27 h1
  text "7" at 39.753,27 h1
  text "BUTTON" at 70,26.5 h1.2
  text "SHT30 Humidity" at 36.753,25 h1
  text "8" at 39.753,25 h1
  text "2" at 21.253,24.5 h3
  text "7" at 46.003,24.5 h3
  text "RESET" at 75.5,24.5 h1
  text "3" at 25.753,20.052 h3
  text "4" at 32.003,20.052 h3
  text "5" at 38.253,20.052 h3
  text "6" at 44.503,20.052 h3
  text "Front side" at 75.25,18.25 h1
  text "INPUT Voltage range (BAT Connector) : 8-30V DC / INPUT SOLAR : Use SOLAR CHARGER board" at 58.75,15.5 h1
